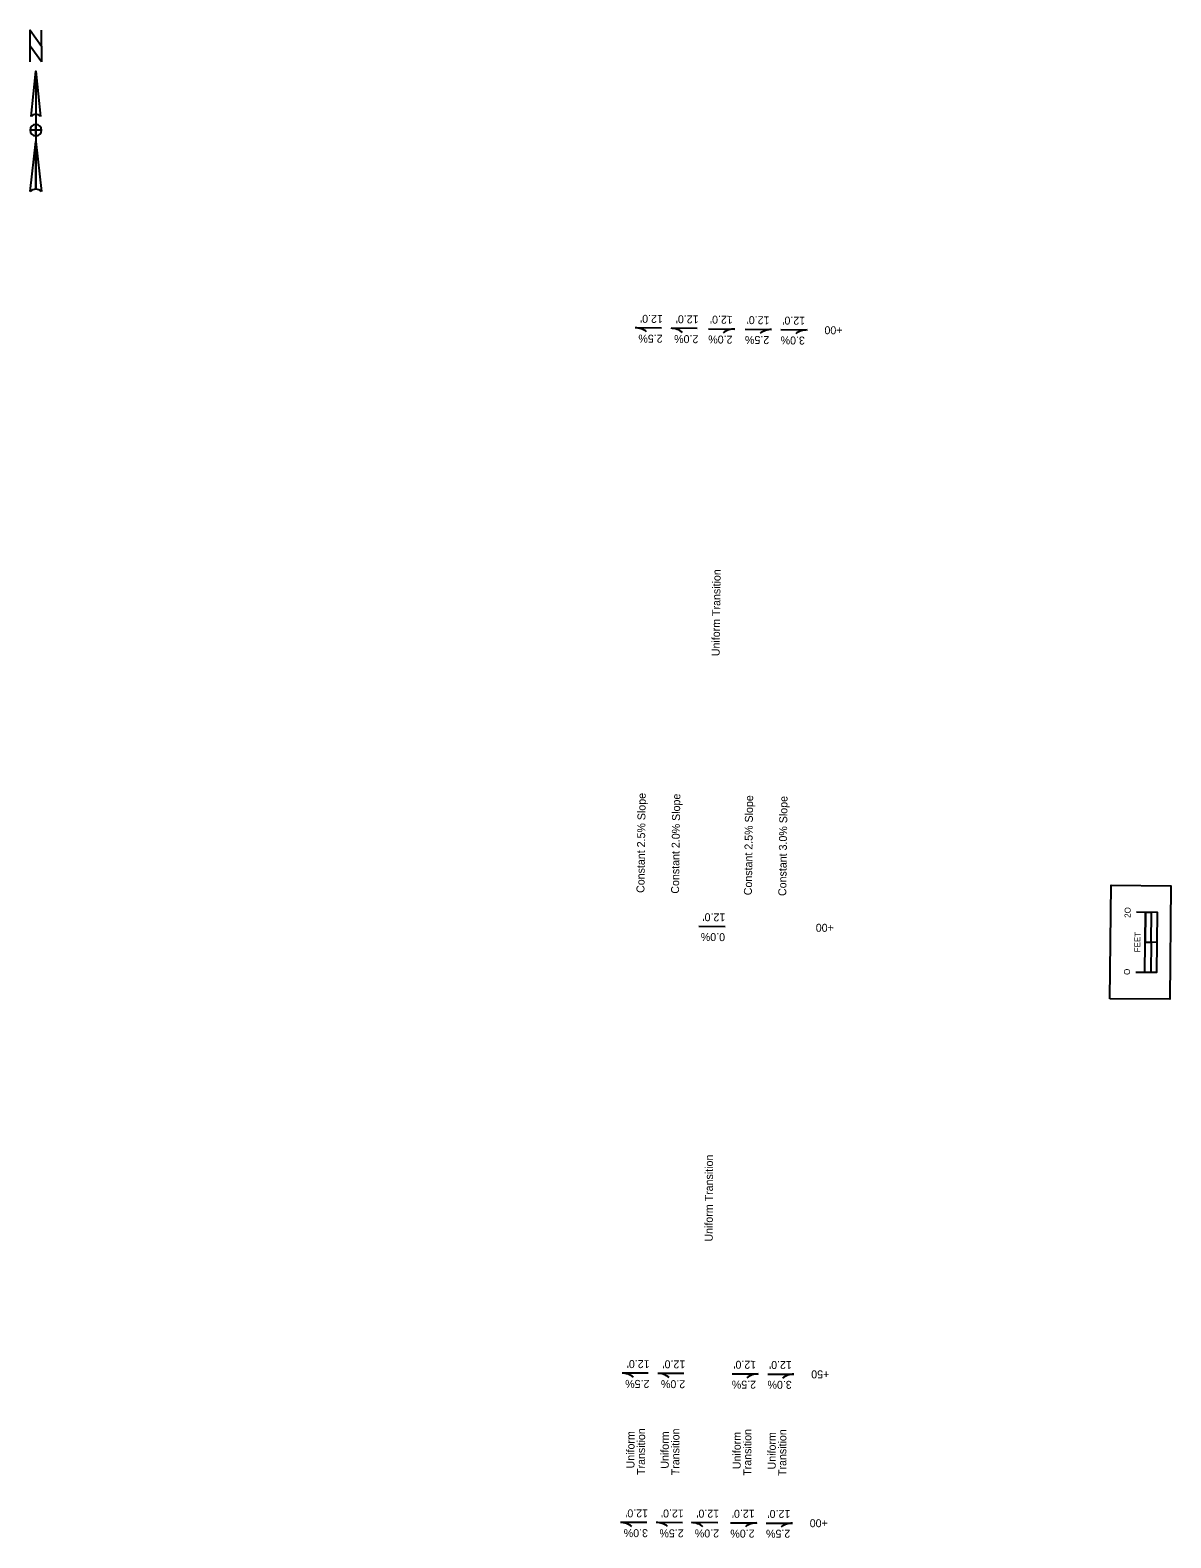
# Model space of a CAD drawing. Extents: x 20505303 to 20506906, y 7965397 to 7979025.
# Drawn here: x 20506430 to 20506812, y 7965397 to 7965901 of the extents above; entities that cross this region are included whole.
import ezdxf

# ---------------------------------------------------------------- set-up
doc = ezdxf.new("R2010")
doc.units = 0
doc.layers.add('_CIVIL_CONSTRUCTION', color=7, linetype='Continuous')
doc.layers.add('Alignment', color=7, linetype='Continuous')

msp = doc.modelspace()

# ---------------------------------------------------------------- linework, layer by layer
at = {"layer": '_CIVIL_CONSTRUCTION'}
for p, q in [((20506432.07, 7965887.55), (20506433.59, 7965872.33)), ((20506432.07, 7965887.55), (20506432.07, 7965848)), ((20506430.55, 7965872.33), (20506430.55, 7965872.33)), ((20506430.61, 7965872.48), (20506430.89, 7965872.79)), ((20506430.17, 7965847.23), (20506432.07, 7965863.97)), ((20506432.07, 7965865.87), (20506432.07, 7965865.87))]:
    msp.add_line(p, q, dxfattribs=at)
msp.add_lwpolyline([(20506433.97, 7965890.59), (20506430.17, 7965895.91), (20506430.17, 7965901.24), (20506433.97, 7965895.91)], close=True, dxfattribs=at)
for points in [[(20506430.17, 7965890.59), (20506430.17, 7965901.24), (20506433.97, 7965895.91), (20506433.97, 7965901.24)], [(20506430.55, 7965872.33), (20506432.07, 7965887.55), (20506432.07, 7965873.1)], [(20506432.07, 7965865.87), (20506432.07, 7965867.77), (20506430.17, 7965867.77)], [(20506433.97, 7965867.77), (20506432.07, 7965867.77), (20506432.07, 7965869.67)], [(20506432.07, 7965848), (20506432.07, 7965863.97), (20506433.97, 7965847.23)]]:
    msp.add_lwpolyline(points, dxfattribs=at)
for centre, radius, start, end in [((20506432.07, 7965871.19), 1.9, 90.0204, 143.1257), ((20506432.07, 7965871.2), 1.9, 36.8481, 90.0218), ((20506432.07, 7965867.77), 1.9, 90, 180), ((20506432.07, 7965867.77), 1.9, 180, 270), ((20506432.07, 7965867.77), 1.9, 0, 90), ((20506432.07, 7965867.77), 1.9, 270, 360), ((20506432.07, 7965845.24), 2.76, 89.9894, 133.619), ((20506432.07, 7965845.24), 2.76, 46.4021, 90.0006)]:
    msp.add_arc(centre, radius, start, end, dxfattribs=at)
at = {"layer": 'Alignment'}
for p, q in [((20506641.51, 7965801.51), (20506632.74, 7965801.62)), ((20506653.48, 7965801.36), (20506644.71, 7965801.47)), ((20506657.27, 7965801.31), (20506666.04, 7965801.2)), ((20506669.56, 7965801.16), (20506678.33, 7965801.05)), ((20506681.5, 7965801.01), (20506690.27, 7965800.9)), ((20506654.04, 7965601.34), (20506662.81, 7965601.23)), ((20506807.45, 7965595.93), (20506803.45, 7965595.97)), ((20506807.45, 7965595.93), (20506803.45, 7965595.97)), ((20506637.08, 7965451.71), (20506628.31, 7965451.77)), ((20506649.04, 7965451.64), (20506640.27, 7965451.69)), ((20506665.13, 7965451.53), (20506673.9, 7965451.48)), ((20506677.07, 7965451.46), (20506685.84, 7965451.4)), ((20506636.58, 7965401.77), (20506627.81, 7965401.81)), ((20506648.54, 7965401.72), (20506639.77, 7965401.76)), ((20506660.38, 7965401.65), (20506651.61, 7965401.74)), ((20506664.63, 7965401.66), (20506673.4, 7965401.62)), ((20506676.57, 7965401.61), (20506685.34, 7965401.57))]:
    msp.add_line(p, q, dxfattribs=at)
for points in [[(20506791.66, 7965577.08), (20506792.04, 7965615.08), (20506812.04, 7965614.88), (20506811.66, 7965576.88)], [(20506791.66, 7965577.08), (20506792.04, 7965615.08), (20506812.04, 7965614.88), (20506811.66, 7965576.88)], [(20506805.44, 7965595.95), (20506805.54, 7965605.95), (20506803.55, 7965605.97), (20506803.45, 7965595.97)], [(20506807.35, 7965585.93), (20506807.45, 7965595.93), (20506805.44, 7965595.95), (20506805.34, 7965585.95)]]:
    msp.add_lwpolyline(points, close=True, dxfattribs=at)
for points in [[(20506800.35, 7965586), (20506807.35, 7965585.93), (20506807.55, 7965605.93), (20506800.55, 7965606)], [(20506803.35, 7965585.97), (20506803.55, 7965605.97)]]:
    msp.add_lwpolyline(points, dxfattribs=at)
for centre, start, end in [((20506632.66, 7965795.46), 51.076, 89.2791), ((20506644.63, 7965795.31), 51.076, 89.2791), ((20506665.96, 7965795.04), 89.2791, 127.4821), ((20506678.26, 7965794.88), 89.2791, 127.4821), ((20506690.19, 7965794.73), 89.2791, 127.4821), ((20506628.27, 7965445.6), 51.4353, 89.6384), ((20506640.23, 7965445.53), 51.4353, 89.6384), ((20506673.86, 7965445.32), 89.6384, 127.8414), ((20506685.8, 7965445.24), 89.6384, 127.8414), ((20506627.78, 7965395.64), 51.5603, 89.7634), ((20506639.75, 7965395.6), 51.5603, 89.7634), ((20506651.55, 7965395.57), 51.2376, 89.4407), ((20506673.38, 7965395.46), 89.7634, 127.9664), ((20506685.32, 7965395.41), 89.7634, 127.9664)]:
    msp.add_arc(centre, 6.16, start, end, dxfattribs=at)

# ---------------------------------------------------------------- texts
for s, height, rotation, p in [("12.0'", 2.664, 179.3818, (20506642, 7965805.9)), ("12.0'", 2.664, 179.3818, (20506653.96, 7965805.75)), ("12.0'", 2.664, 179.3818, (20506665.4, 7965805.61)), ("12.0'", 2.664, 179.3818, (20506677.69, 7965805.45)), ("12.0'", 2.664, 179.3818, (20506689.63, 7965805.3)), ('+00', 2.664, 179.3818, (20506702.13, 7965802.09)), ('2.5%', 2.664, 179.3818, (20506641.91, 7965799.28)), ('2.0%', 2.664, 179.3818, (20506653.88, 7965799.13)), ('2.0%', 2.664, 179.3818, (20506665.31, 7965798.98)), ('2.5%', 2.664, 179.3818, (20506677.6, 7965798.83)), ('3.0%', 2.664, 179.3818, (20506689.54, 7965798.68)), ('Uniform Transition', 2.664, 89.2905, (20506660.98, 7965691.7)), ('Constant 2.5% Slope', 2.664, 89.2393, (20506635.8, 7965612.47)), ('Constant 2.0% Slope', 2.664, 89.2393, (20506647.38, 7965612.22)), ('Constant 2.5% Slope', 2.664, 89.2393, (20506671.77, 7965611.69)), ('Constant 3.0% Slope', 2.664, 89.2393, (20506683.28, 7965611.44)), ("12.0'", 2.664, 179.3818, (20506662.9, 7965605.62)), ('2O', 2, 89.43, (20506798.53, 7965604.14)), ('0.0%', 2.664, 179.3818, (20506662.81, 7965599)), ('+00', 2.664, 179.3818, (20506699.22, 7965602.11)), ('FEET', 2, 89.43, (20506801.82, 7965592.6)), ('O', 2, 89.43, (20506798.34, 7965585.03)), ('Uniform Transition', 2.664, 89.7569, (20506658.67, 7965495.79)), ("12.0'", 2.664, 179.7411, (20506637.54, 7965456.1)), ("12.0'", 2.664, 179.7411, (20506649.5, 7965456.03)), ("12.0'", 2.664, 179.7411, (20506673.23, 7965455.88)), ("12.0'", 2.664, 179.7411, (20506685.17, 7965455.8)), ('+50', 2.664, 179.7411, (20506697.69, 7965452.67)), ('2.5%', 2.664, 179.7411, (20506637.49, 7965449.48)), ('2.0%', 2.664, 179.7411, (20506649.46, 7965449.4)), ('2.5%', 2.664, 179.7411, (20506673.19, 7965449.25)), ('3.0%', 2.664, 179.7411, (20506685.13, 7965449.18)), ('Transition', 2.664, 89.7569, (20506635.99, 7965417.67)), ('Transition', 2.664, 89.7569, (20506647.48, 7965417.59)), ('Transition', 2.664, 89.7569, (20506671.57, 7965417.42)), ('Transition', 2.664, 89.7569, (20506683.28, 7965417.34)), ('Uniform', 2.664, 89.7569, (20506632.46, 7965419.87)), ('Uniform', 2.664, 89.7569, (20506643.94, 7965419.79)), ('Uniform', 2.664, 89.7569, (20506668.03, 7965419.62)), ('Uniform', 2.664, 89.7569, (20506679.75, 7965419.54)), ("12.0'", 2.664, 179.8661, (20506637.03, 7965406.17)), ("12.0'", 2.664, 179.8661, (20506648.99, 7965406.12)), ("12.0'", 2.664, 179.8661, (20506660.83, 7965406.07)), ("12.0'", 2.664, 179.8661, (20506672.72, 7965406.02)), ("12.0'", 2.664, 179.8661, (20506684.66, 7965405.97)), ('+00', 2.664, 179.8661, (20506697.19, 7965402.86)), ('3.0%', 2.664, 179.8661, (20506637, 7965399.54)), ('2.5%', 2.664, 179.8661, (20506648.96, 7965399.49)), ('2.0%', 2.664, 179.8661, (20506660.8, 7965399.44)), ('2.0%', 2.664, 179.8661, (20506672.69, 7965399.39)), ('2.5%', 2.664, 179.8661, (20506684.63, 7965399.35))]:
    msp.add_text(s, height=height, rotation=rotation, dxfattribs=at).set_placement(p)

doc.saveas('drawing.dxf')
